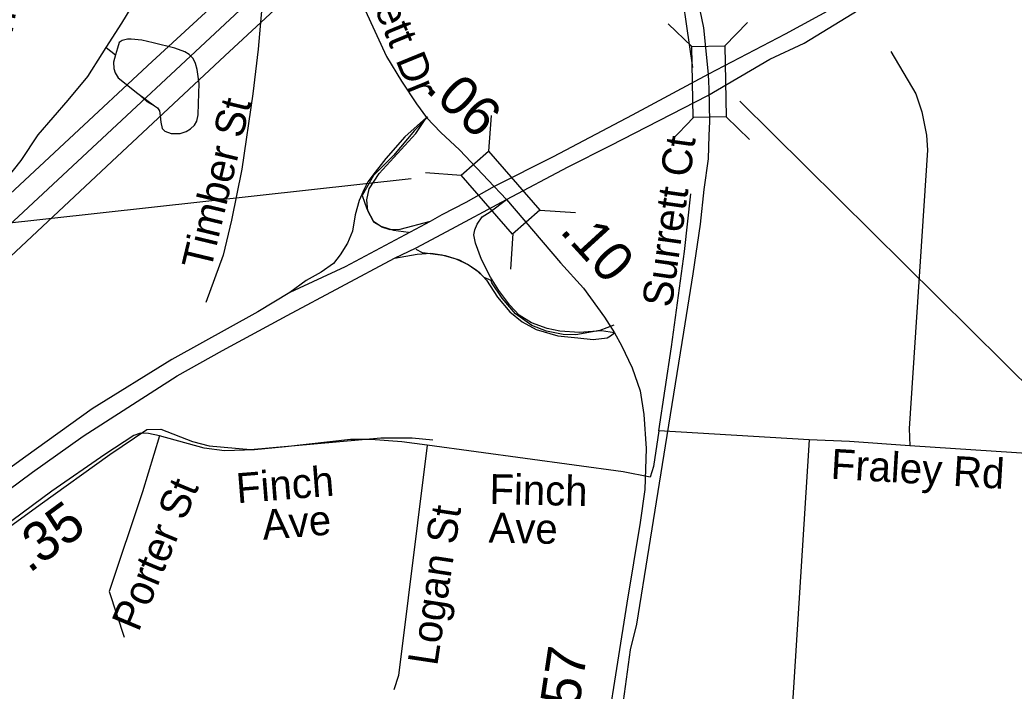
# Model space of a CAD drawing. Extents: x 1662474 to 1856135, y 779280 to 917889.
# Drawn here: x 1701997 to 1705150, y 793367 to 795494 of the extents above; entities that cross this region are included whole.
import ezdxf

# ---------------------------------------------------------------- set-up
doc = ezdxf.new("R2010")
doc.units = 0
for name, color, linetype in [('Exist Hydrographic Misc Water Feature', 7, 'Continuous'), ('Exist Railroad Mainline', 7, 'Continuous'), ('Exist Railroad Structure Bridge CELL', 7, 'Continuous'), ('Exist Railroad Structure Bridge Number Label', 7, 'Continuous'), ('Exist Road Non-System Type 51', 7, 'Continuous'), ('Exist Road Non-System Type 51 Label', 7, 'Continuous'), ('Exist Road Primary Interstate Divided Center Attributed', 7, 'Continuous'), ('Exist Road Primary Interstate Ramp 1 Lane Attributed', 7, 'Continuous'), ('Exist Road Primary Interstate Service Attributed', 7, 'Continuous'), ('Exist Road Primary Interstate Service Mileage Tenths English Label', 7, 'Continuous'), ('Exist Road Secondary Structure Standard Bridge CELL', 7, 'Continuous'), ('Exist Road Secondary Structure Standard Bridge Number Label', 7, 'Continuous'), ('Exist Road Secondary Type 51 Attributed', 7, 'Continuous'), ('Exist Road Secondary Type 51 Label', 7, 'Continuous'), ('Exist Utilities Electrical Transmission Line', 7, 'Continuous'), ('Prop DGN Element Guardrail', 7, 'Continuous')]:
    doc.layers.add(name, color=color, linetype=linetype)

msp = doc.modelspace()

# ---------------------------------------------------------------- linework, layer by layer
at = {"layer": 'Exist Hydrographic Misc Water Feature'}
msp.add_line((1702270.2, 795406.7), (1702300.1, 795383.1), dxfattribs=at)
for points in [[(1702270.2, 795406.7), (1702320.3, 795483.6), (1702376.4, 795576.9), (1702461.1, 795754.8), (1702577.7, 795960.1), (1702635.9, 796030.3), (1702672.2, 796054.2), (1702708.2, 796079.7), (1702734.4, 796107.9), (1702756.3, 796140.3), (1702782.7, 796231.6), (1702806.9, 796265.6), (1702849, 796297.6), (1702903, 796317), (1702987, 796343.2), (1703051.1, 796345.2), (1703096.1, 796339.3)], [(1702300.1, 795383.1), (1702294.1, 795360.2), (1702294.6, 795340.5), (1702298.8, 795326.5), (1702308.7, 795310.8), (1702371.1, 795261.1), (1702399.6, 795235.9), (1702423.7, 795222.2), (1702433.2, 795215.5), (1702439.7, 795206.3), (1702441.8, 795189.9), (1702444.1, 795170.1), (1702448.2, 795150.3), (1702456.3, 795142), (1702476.5, 795134.2), (1702504.6, 795134.4), (1702523.7, 795140.6), (1702538.3, 795149.3), (1702550.2, 795160.6), (1702558.1, 795173.6), (1702561.9, 795193.2), (1702563.4, 795229.2), (1702565, 795293.2), (1702558.6, 795337.6), (1702553.9, 795356.6), (1702546.3, 795371.6), (1702533.8, 795384.1), (1702520.1, 795392.6), (1702487.8, 795404.8), (1702419.7, 795421.7), (1702383.6, 795429.8), (1702349.6, 795433), (1702337.7, 795433.3), (1702321.6, 795428.6), (1702311.5, 795423.1), (1702306, 795404.3), (1702300.1, 795383.1)], [(1702300.1, 795383.1), (1702294.1, 795360.2), (1702294.6, 795340.5), (1702298.8, 795326.5), (1702308.7, 795310.8), (1702371.1, 795261.1), (1702423.7, 795222.2), (1702433.2, 795215.5), (1702439.7, 795206.3), (1702441.8, 795189.9), (1702444.1, 795170.1), (1702448.2, 795150.3), (1702456.3, 795142), (1702476.5, 795134.2), (1702504.6, 795134.4), (1702523.7, 795140.6), (1702538.3, 795149.3), (1702550.2, 795160.6), (1702558.1, 795173.6), (1702561.9, 795193.2), (1702563.4, 795229.2), (1702565, 795293.2), (1702558.6, 795337.6), (1702553.9, 795356.6), (1702546.3, 795371.6), (1702533.8, 795384.1), (1702520.1, 795392.6), (1702487.8, 795404.8), (1702419.7, 795421.7), (1702383.6, 795429.8), (1702349.6, 795433), (1702337.7, 795433.3), (1702321.6, 795428.6), (1702311.5, 795423.1), (1702306, 795404.3), (1702300.1, 795383.1)], [(1701882.4, 794900.9), (1702000.8, 795048.6), (1702054.9, 795130.4), (1702149.5, 795240.1), (1702211.8, 795315.1), (1702257.9, 795387.2), (1702270.2, 795406.7)]]:
    msp.add_lwpolyline(points, dxfattribs=at)
at = {"layer": 'Exist Railroad Mainline'}
msp.add_lwpolyline([(1703904.2, 793289.3), (1703933.5, 793498.1), (1703953, 793579.2), (1703992, 793822.8), (1704044, 794144.2), (1704102.5, 794504.7), (1704131.8, 794689.8), (1704155.1, 794846.5), (1704166.2, 794956.9), (1704179.9, 795053.9), (1704182.8, 795127.9), (1704184.7, 795172.8), (1704182.1, 795277.3), (1704181.9, 795298.4), (1704180.2, 795322.6), (1704165.4, 795469.5), (1704148.6, 795550.1)], dxfattribs=at)
at = {"layer": 'Exist Railroad Structure Bridge CELL'}
for p, q in [((1704053, 795481.4), (1704127.1, 795410.1)), ((1704303.8, 795486.2), (1704232.4, 795412)), ((1704133.3, 795184.8), (1704061.9, 795110.7)), ((1704236.2, 795186.7), (1704310.3, 795115.4))]:
    msp.add_line(p, q, dxfattribs=at)
msp.add_lwpolyline([(1704232.4, 795412), (1704236.7, 795186.7), (1704131.4, 795184.7), (1704127.1, 795410.1)], close=True, dxfattribs=at)
at = {"layer": 'Exist Railroad Structure Bridge Number Label'}
msp.add_line((1704279.7, 795236.4), (1706118.7, 793417.4), dxfattribs=at)
at = {"layer": 'Exist Road Non-System Type 51'}
for p, q in [((1704499.9, 794164.1), (1704022.8, 794192.2)), ((1704499.9, 794164.1), (1704380.8, 792298.8)), ((1705436.1, 794104), (1704818.8, 794144.9))]:
    msp.add_line(p, q, dxfattribs=at)
for points in [[(1703872.9, 796759.1), (1703933, 796507.1), (1703991.8, 796195.4), (1704019.9, 796018.9), (1704080.1, 795686.9), (1704129.2, 795343.4)], [(1702941.4, 795905.2), (1702927.5, 795907.4), (1702910.6, 795898.2), (1702809.9, 795779.9), (1702793.4, 795747.9), (1702785.8, 795725.5), (1702770, 795608.4), (1702751.9, 795401.9), (1702735.1, 795260.2), (1702700.1, 795021.6), (1702668.1, 794859.9), (1702640.9, 794749.2), (1702586.9, 794598.8)], [(1704758.4, 795393.8), (1704837.9, 795260.2), (1704856.9, 795202.7), (1704871.5, 795128.9), (1704874.6, 795081.9), (1704817.1, 794199.5), (1704818.8, 794144.9)], [(1703289.9, 795187.4), (1703248.5, 795143.9), (1703181.2, 795064.1), (1703118, 795000.9), (1703082.6, 794937.9), (1703097, 794896.1), (1703119.4, 794853.6), (1703141.4, 794840.8), (1703181, 794827.9), (1703229.4, 794821.4)], [(1704022.8, 794192.2), (1704063.1, 794458.4), (1704104.1, 794760.7), (1704124.6, 794942.9)], [(1703880.5, 794526.6), (1703835.4, 794509.8), (1703759.2, 794496.1), (1703719.1, 794497.7), (1703666.4, 794507.7), (1703619.9, 794526.4), (1703568.1, 794563.1), (1703525.6, 794612.1), (1703492.9, 794660.9), (1703491, 794668.2), (1703468.9, 794678.5), (1703446.4, 794699), (1703418.5, 794717.7), (1703391, 794732.6), (1703346.9, 794746.5), (1703273.1, 794755.7), (1703253.8, 794766.4)], [(1704022.8, 794192.2), (1704005.6, 794078.9), (1703995.1, 794045.8)], [(1702439, 794176.2), (1702404.1, 794184.1), (1702379.4, 794185.1), (1702358.1, 794177.8), (1702266.6, 794117.4), (1702097.9, 794000.6), (1701414.6, 793494.9), (1701392.4, 793472.2), (1701389.1, 793464.1), (1701378.6, 793435.8), (1701378.6, 793372.5), (1701392.6, 792827.1)], [(1702439, 794176.2), (1702385.2, 793998.8), (1702279.8, 793683), (1702327.8, 793538.4)], [(1703287.9, 794146.5), (1703207.5, 794157.5), (1703109.6, 794164.9), (1703045.4, 794165.2), (1702839.2, 794141), (1702741.1, 794132.4), (1702646.1, 794128.4), (1702581.2, 794137.6), (1702439, 794176.2)], [(1704818.8, 794144.9), (1704627.4, 794158.4), (1704499.9, 794164.1)], [(1703287.9, 794146.5), (1703197, 793416.6), (1703183.1, 793371.5)], [(1703995.1, 794045.8), (1703910.1, 794062.5), (1703287.9, 794146.5)]]:
    msp.add_lwpolyline(points, dxfattribs=at)
at = {"layer": 'Exist Road Primary Interstate Divided Center Attributed'}
for points in [[(1705590.5, 796146.6), (1705375.7, 796016.4), (1705051.1, 795807.8), (1704798.5, 795654.1), (1704424, 795449.2), (1704180.2, 795322.6)], [(1704178.7, 795254.8), (1704374.6, 795369.5), (1704483.3, 795420.2), (1704812.7, 795622.8), (1705087.3, 795781.1), (1705354.6, 795961.9), (1705527.4, 796074.5)], [(1704180.2, 795322.6), (1703938.6, 795192.5), (1703688.2, 795060.2), (1703501, 794966)], [(1703539.4, 794925.5), (1703735.3, 795028.2), (1703869.9, 795095.8), (1704178.7, 795254.8)], [(1703501, 794966), (1703410.8, 794916.1), (1703335.2, 794876.5), (1703298.2, 794855.3)], [(1703184.9, 794739), (1703253.7, 794771.5), (1703351, 794823.7), (1703539.4, 794925.5)], [(1703298.2, 794855.3), (1703027.8, 794712), (1702853.3, 794630.4)], [(1700381.7, 792830.1), (1700522.6, 792935.7), (1700907.4, 793226.8), (1701330.4, 793540.5), (1701557.2, 793709.6), (1701883.2, 793948.4), (1702037, 794061.4), (1702197.8, 794175), (1702495.5, 794366.2), (1702639.7, 794446.7), (1702844.8, 794557.1), (1703184.9, 794739)], [(1702853.3, 794630.4), (1702750.9, 794569.7), (1702479, 794418), (1702226.1, 794261.6), (1702015.2, 794111.1), (1701830, 793976.6), (1701479.5, 793719.9), (1701237.6, 793540), (1700863.6, 793263), (1700730.9, 793171.6), (1700489.1, 792985.6), (1700346.4, 792876.8)]]:
    msp.add_lwpolyline(points, dxfattribs=at)
at = {"layer": 'Exist Road Primary Interstate Ramp 1 Lane Attributed'}
for points in [[(1703285.9, 795185.4), (1703217, 795123.6), (1703157.1, 795054.8), (1703116.5, 795001.8), (1703100.6, 794980.7), (1703088.3, 794957.7), (1703072.4, 794922.4), (1703060, 794876.5), (1703051.2, 794825.3), (1703035.3, 794786.5), (1703012.4, 794749.4), (1702991.2, 794722.9), (1702952.4, 794694.7), (1702904.8, 794668.2), (1702853.3, 794630.4)], [(1703298.2, 794855.3), (1703201.2, 794830.6), (1703171.2, 794828.8), (1703144.7, 794837.7), (1703118.3, 794855.3), (1703100.6, 794888.9), (1703097.1, 794924.2), (1703104.1, 794959.5), (1703135.9, 795007.1), (1703252.3, 795134.2), (1703285.9, 795185.4)], [(1703550.6, 794590), (1703515.2, 794636.4), (1703488.7, 794678.8), (1703460.5, 794735.3), (1703441.1, 794786.5), (1703435.8, 794813), (1703439.3, 794828.8), (1703446.4, 794846.5), (1703463.1, 794869.9), (1703487.6, 794886.4), (1703539.4, 794925.5)], [(1703184.9, 794739), (1703256.1, 794751.7), (1703299.9, 794755.4), (1703335.2, 794749.4), (1703379.4, 794737.1), (1703418.2, 794719.4), (1703453.4, 794694.7), (1703476.4, 794670), (1703511.7, 794615.3), (1703550.5, 794569.4), (1703589.3, 794537.6), (1703633.4, 794512.9), (1703702.2, 794493.5), (1703765.7, 794486.4), (1703815.1, 794481.1), (1703859.2, 794486.4), (1703869.8, 794493.5), (1703882.1, 794502.3)], [(1703882.1, 794502.3), (1703841.6, 794509.3), (1703771, 794504.1), (1703709.3, 794507.6), (1703668.7, 794516.4), (1703619.3, 794534.1), (1703580.5, 794558.8), (1703550.6, 794590)]]:
    msp.add_lwpolyline(points, dxfattribs=at)
at = {"layer": 'Exist Road Primary Interstate Service Attributed'}
msp.add_lwpolyline([(1701393.8, 792831.7), (1701386.5, 792932.5), (1701366.2, 793307.1), (1701366.7, 793429.2), (1701377.1, 793455), (1701426.8, 793498), (1702061.5, 793958.6), (1702282.1, 794117.7), (1702399.3, 794196.2), (1702444.2, 794197.8), (1702543.9, 794158.6), (1702597.5, 794144.8), (1702728.1, 794133.4), (1703140.9, 794170.4), (1703241, 794170.3), (1703306.2, 794164)], dxfattribs=at)
at = {"layer": 'Exist Road Secondary Structure Standard Bridge CELL'}
for p, q in [((1703491, 795191.6), (1703483.2, 795078.7)), ((1703282.9, 795010.5), (1703395.8, 795002.7)), ((1703645.5, 794891.3), (1703758.4, 794883.5)), ((1703560.1, 794817), (1703552.2, 794704.1))]:
    msp.add_line(p, q, dxfattribs=at)
msp.add_lwpolyline([(1703483.2, 795078.7), (1703645.9, 794891.7), (1703558.5, 794815.7), (1703395.8, 795002.7)], close=True, dxfattribs=at)
at = {"layer": 'Exist Road Secondary Structure Standard Bridge Number Label'}
msp.add_line((1703237.3, 794990.8), (1701205.9, 794766.6), dxfattribs=at)
at = {"layer": 'Exist Road Secondary Type 51 Attributed'}
for points in [[(1702565.1, 796765.7), (1702637.3, 796620.6), (1702717.9, 796438), (1702812.1, 796201.2), (1702957.8, 795849.6), (1703031.1, 795662.6), (1703092, 795525.3), (1703159.4, 795378.8), (1703206.9, 795299.6), (1703254.5, 795228.4), (1703285.9, 795185.4)], [(1703501, 794966), (1703391.2, 795082.3), (1703332, 795137.4), (1703285.9, 795185.4)], [(1703539.4, 794925.5), (1703520.8, 794945.3), (1703501, 794966)], [(1703539.4, 794925.5), (1703711.1, 794725), (1703784.4, 794644.7), (1703850.6, 794552.6), (1703882.1, 794502.3)], [(1703882.1, 794502.3), (1703904.9, 794462.9), (1703938, 794392.1), (1703964, 794318.9), (1703975.8, 794244.3), (1703982.9, 794135.7), (1703978.2, 794005.9), (1703964, 793902), (1703921.5, 793646.3), (1703829.4, 793065.1), (1703801.1, 792876.3), (1703775.1, 792692.1), (1703763.3, 792569.4), (1703765.8, 792455.1), (1703783.3, 792244.4), (1703810.3, 791999.9), (1703846.8, 791709.2), (1703864.7, 791544.9)]]:
    msp.add_lwpolyline(points, dxfattribs=at)
at = {"layer": 'Exist Utilities Electrical Transmission Line'}
for points in [[(1704137.3, 796780.5), (1703839.6, 796606.2), (1703655.1, 796491.1), (1703482.1, 796342.3), (1703035.9, 795932.6), (1702754.3, 795674.4), (1702416.4, 795362.5), (1702152.8, 795117.8), (1701885.5, 794869.5), (1701619.8, 794622.8), (1701475.4, 794491.8), (1701332.6, 794362.4), (1701251, 794418.9), (1701185.6, 794575.5), (1701126.7, 794746)], [(1704176.7, 796741.9), (1703861.4, 796548), (1703690.7, 796431), (1703099.6, 795902.8), (1701742.3, 794638.8), (1701249.7, 794222.9), (1701018.9, 794076.3), (1700799.5, 793859.5), (1700485.9, 793563.3), (1700145.8, 793239.3), (1699828.1, 792932.9), (1699560.7, 792676.4), (1699238.8, 792376.4), (1698967.3, 792115.7), (1698848.5, 792002.6), (1698780.1, 791948.8), (1698452.8, 791705), (1698238, 791554.1), (1697906.8, 791173.4)], [(1704303, 796746.1), (1703891.2, 796491.9), (1703732.7, 796382.9), (1703603.9, 796265.3), (1703350.3, 796026.9), (1703004.5, 795712.9), (1702646.5, 795380.8), (1702288.8, 795045.1), (1701898.4, 794681.1), (1701550.5, 794361.3), (1701329.2, 794162.6), (1701070.3, 794003.7), (1700847.2, 793799.2), (1700523.3, 793495.2), (1700131.3, 793123.4), (1699807.4, 792819.1), (1699461.3, 792489.1), (1699192.1, 792226.7), (1698964.9, 792011.7), (1698837.9, 791900.7), (1698506.5, 791650.4), (1698309.9, 791503.8), (1698006.2, 791167.8)]]:
    msp.add_lwpolyline(points, dxfattribs=at)

# ---------------------------------------------------------------- texts
at = {"layer": 'Exist Road Non-System Type 51 Label'}
for s, rotation, p in [('Motsinger St', 79.8459, (1701919.1, 795150.2)), ('Surrett Dr', 292.197, (1703029.7, 795753.6)), ('Timber St', 76.5227, (1702601.6, 794697.1)), ('Surrett Ct', 81.9499, (1704063.5, 794580.5)), ('Fraley Rd', 356.6264, (1704566.4, 794040.8)), ('Porter St', 67.4335, (1702372.8, 793552.2)), ('Finch ', 358.7559, (1703485.1, 793960.3)), ('Logan St', 81.3772, (1703320, 793445)), ('Ave', 358.7559, (1703482.4, 793838.4))]:
    msp.add_text(s, height=95, rotation=rotation, dxfattribs=at).set_placement(p)
at = {"layer": 'Exist Road Primary Interstate Service Mileage Tenths English Label'}
msp.add_text('.35', height=125, rotation=36.2498, dxfattribs=at).set_placement((1702026.2, 793739.2))
at = {"layer": 'Exist Road Secondary Type 51 Label'}
for s, p in [('Finch ', (1702686.3, 793962.5)), ('Ave', (1702768.5, 793846.6))]:
    msp.add_text(s, height=95, rotation=4.523, dxfattribs=at).set_placement(p)
at = {"layer": 'Prop DGN Element Guardrail'}
for s, rotation, p in [('.06', 317.1376, (1703278.9, 795271.9)), ('.10', 312.3883, (1703705.5, 794823.8)), ('.57', 81.4601, (1703762.6, 793267.8))]:
    msp.add_text(s, height=125, rotation=rotation, dxfattribs=at).set_placement(p)

doc.saveas('drawing.dxf')
